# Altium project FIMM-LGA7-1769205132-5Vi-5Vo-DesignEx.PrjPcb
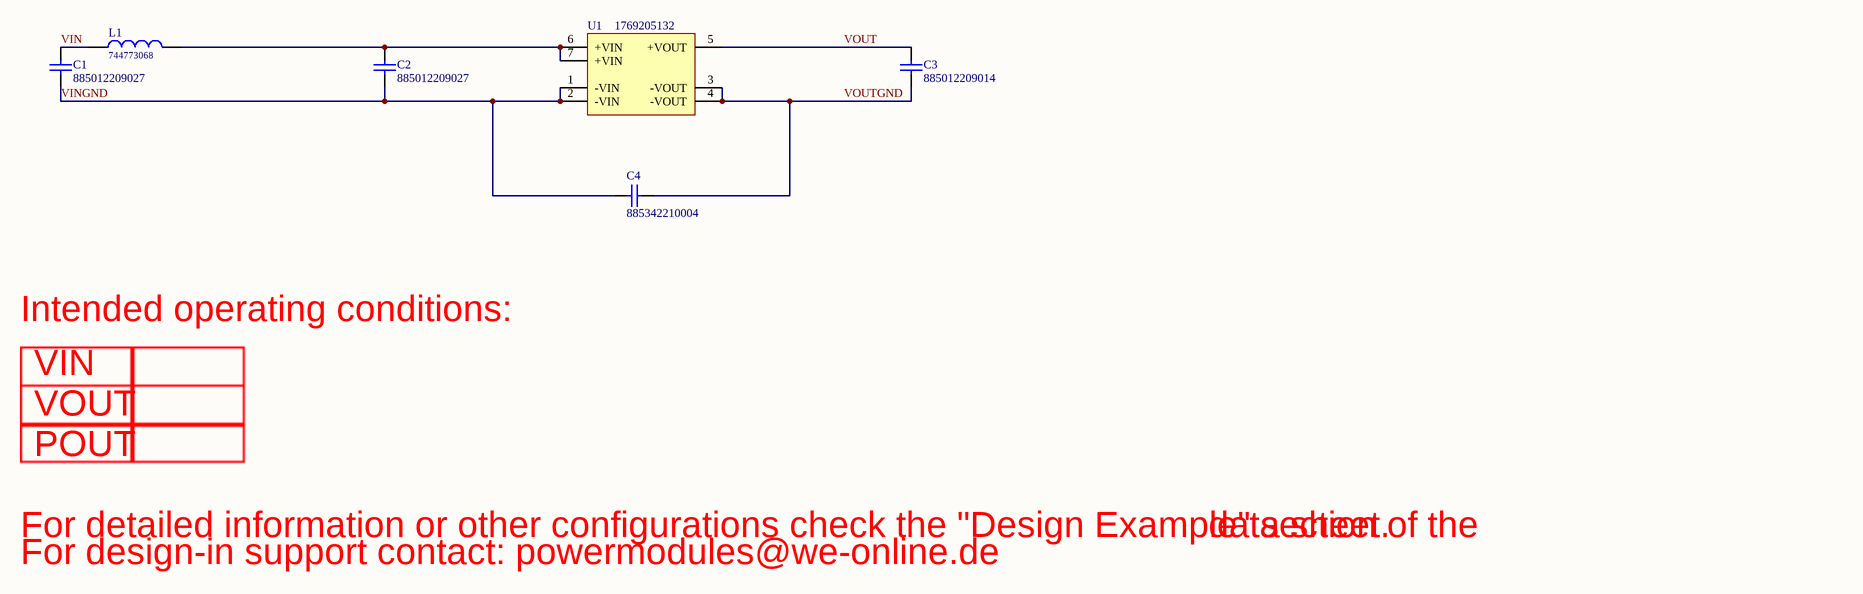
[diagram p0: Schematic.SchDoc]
PN: 1769205132; VOUT: 5V; VIN: 5V; POUT: 1W
1 sheet, 6 parts. Net scope: global (net labels, ports and power ports of the same name join across sheets).
Board file: PCB.PcbDoc

## Sheet Schematic.SchDoc: 1769205132 Design Example (5Vin 5Vout)
size A3; CompanyName: Würth Elektronik; DrawnBy: WE; Organization: Würth Elektronik; Revision: 1.0; SheetNumber: 1; SheetTotal: 1; PageSetup: Record=PageOptions¦CenterHorizontal=True¦CenterVertical=True¦PrintScale=0.97¦XCorrection=1.00¦YCorrection=1.00¦PrintKind=0¦BorderSize=5000000¦LeftOffset=0¦BottomOffset=0¦Orientation=1¦PaperLength=1000¦PaperWidth=1000¦Scale=100¦PaperSource=7¦PrintQuality=600¦MediaType=1¦DitherType=10¦PaperKind=A4¦PrintScaleMode=1; PCBNumber: 1; ProjectNumber: 1

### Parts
C1  885012209027  [WCAP-CSGP_1210_H=2mm]
C2  885012209027  [WCAP-CSGP_1210_H=2mm]
C3  885012209014  [WCAP-CSGP_1210_H=2mm]
C4  885342210004  [WCAP-CSMH_1808_H2]
L1  744773068  [WE-PD2_4532]
U1  1769205132  [WPME-FIMM_LGA-7_L9W7H3.1]

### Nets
VIN: C1.2 L1.1
VINGND: C1.1 C2.1 C4.1 U1.1(-VIN) U1.2(-VIN)
VOUT: C3.2 U1.5(+VOUT)
VOUTGND: C3.1 C4.2 U1.3(-VOUT) U1.4(-VOUT)
NetC2_2: C2.2 L1.2 U1.6(+VIN) U1.7(+VIN)

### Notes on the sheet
- Intended operating conditions:
- VIN
- VOUT
- POUT
- For detailed information or other configurations check the "Design Example" section of the
- For design-in support contact: powermodules@we-online.de
- data sheet.

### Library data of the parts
C1 C2 = CMP-051-000886-10: WCAP-CSGP Multilayer Ceramic Chip Capacitor, General Purpose, size 1210, X7R, 4.7uF, 25V; Capacitance Tolerance: +/-10%; Isolation Resistance: >=0.1GOhm; Technical Reference: X7R1210475K025DFCT10000; Rated Voltage: 25VDC
C3 = CMP-051-000873-10: WCAP-CSGP Multilayer Ceramic Chip Capacitor, General Purpose, size 1210, X7R, 10uF, 16V; Technical Reference: X7R1210106K016DFCT10000; Isolation Resistance: >=0.1GOhm; Rated Voltage: 16VDC; Capacitance Tolerance: +/-10%
C4 = CMP-055-000091-5: WCAP-CSMH Multilayer Ceramic Chip Capacitor, size 1808, X7R Class II, 1nF, 3000V; Technical Reference: X7R1808102KC00DFCT10000; Rated Voltage: 3000VDC; Insulation Resistance: 10GOhm; Provided by WE: Yes; Capacitance Tolerance: +/-10%; Dissipation Factor: 2.5%
L1 = CMP-495-000010-A.4: WE-PD2 SMT Power Inductor, size 4532, 6.8uH, 1.54A; Manufacturer: Wurth Elektronik; DC Resistance typ.: 0.076Ohm; Self Resonant Frequency: 41MHz; Saturation Current: 2.1A; DC Resistance max.: 0.131Ohm
U1 = CMP-IC-00008-A.1: WPME-FIMM Fixed Isolated Module, LGA-7, 4.5-5.5Vin, 5Vout; Manufacturer: Wurth Elektronik; Isolation Voltage: 3kV; Output Voltage: 5V; Input Voltage Max: 5.5V; Input Voltage Min: 4.5V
